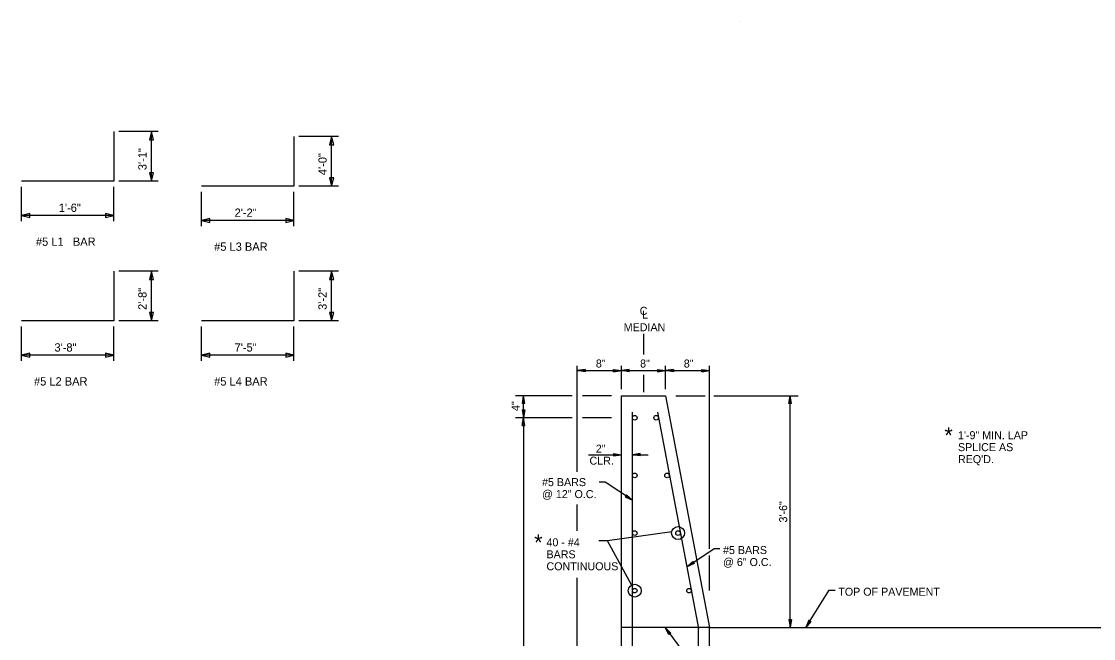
# Model space of a CAD drawing. Extents: x 757924.6 to 757955.2, y 1657125.5 to 1657146.2.
# Drawn here: x 757928.46 to 757944.65, y 1657136.87 to 1657146.19 of the extents above; entities that cross this region are included whole.
import ezdxf

# ---------------------------------------------------------------- set-up
doc = ezdxf.new("R2010")
doc.units = 0
for name, color, linetype in [('1', 7, 'Continuous'), ('2', 7, 'Continuous'), ('7', 7, 'Continuous'), ('9', 7, 'Continuous'), ('R_Border', 7, 'Continuous')]:
    doc.layers.add(name, color=color, linetype=linetype)

msp = doc.modelspace()

# ---------------------------------------------------------------- linework, layer by layer
at = {"layer": '1'}
for p, q in [((757929.851, 1657144.528), (757929.851, 1657143.778)), ((757932.572, 1657144.454), (757932.572, 1657143.704)), ((757929.851, 1657143.778), (757928.455, 1657143.778)), ((757932.572, 1657143.704), (757931.176, 1657143.704)), ((757929.851, 1657142.418), (757929.851, 1657141.669)), ((757932.572, 1657142.418), (757932.572, 1657141.669)), ((757929.851, 1657141.669), (757928.455, 1657141.669)), ((757932.572, 1657141.669), (757931.176, 1657141.669)), ((757937.85, 1657141.472), (757937.85, 1657141.164)), ((757937.85, 1657140.857), (757937.85, 1657140.592)), ((757937.517, 1657135.539), (757937.517, 1657140.539)), ((757937.517, 1657140.539), (757938.184, 1657140.539)), ((757938.184, 1657140.539), (757938.85, 1657137.039)), ((757937.684, 1657135.523), (757937.684, 1657140.289)), ((757938.062, 1657140.289), (757938.684, 1657137.023)), ((757938.85, 1657137.039), (757937.517, 1657137.039)), ((757938.684, 1657132.641), (757938.684, 1657137.023)), ((757938.85, 1657129.997), (757938.85, 1657137.039)), ((757938.85, 1657137.039), (757945.177, 1657137.039))]:
    msp.add_line(p, q, dxfattribs=at)
for centre in [(757937.719, 1657140.206), (757938.043, 1657140.206), (757937.719, 1657139.335), (757938.208, 1657139.335), (757937.719, 1657138.465), (757938.374, 1657138.465), (757937.719, 1657137.595), (757938.54, 1657137.595)]:
    msp.add_circle(centre, 0.0349, dxfattribs=at)
at = {"layer": '7'}
for p, q in [((757936.969, 1657140.937), (757936.85, 1657140.918)), ((757936.969, 1657140.901), (757936.85, 1657140.918)), ((757936.969, 1657140.934), (757936.87, 1657140.918)), ((757936.969, 1657140.904), (757936.87, 1657140.918)), ((757936.969, 1657140.93), (757936.891, 1657140.918)), ((757936.969, 1657140.907), (757936.891, 1657140.918)), ((757936.969, 1657140.928), (757936.911, 1657140.918)), ((757936.969, 1657140.91), (757936.911, 1657140.918)), ((757936.969, 1657140.924), (757936.931, 1657140.918)), ((757936.969, 1657140.913), (757936.931, 1657140.918)), ((757936.969, 1657140.921), (757936.951, 1657140.918)), ((757936.969, 1657140.916), (757936.951, 1657140.918)), ((757936.969, 1657140.937), (757936.969, 1657140.901)), ((757937.397, 1657140.936), (757937.517, 1657140.918)), ((757937.397, 1657140.901), (757937.397, 1657140.936)), ((757937.397, 1657140.933), (757937.497, 1657140.918)), ((757937.397, 1657140.93), (757937.477, 1657140.918)), ((757937.397, 1657140.927), (757937.456, 1657140.918)), ((757937.397, 1657140.924), (757937.436, 1657140.918)), ((757937.397, 1657140.921), (757937.417, 1657140.918)), ((757937.397, 1657140.901), (757937.517, 1657140.918)), ((757937.397, 1657140.913), (757937.436, 1657140.918)), ((757937.397, 1657140.907), (757937.477, 1657140.918)), ((757937.397, 1657140.904), (757937.497, 1657140.918)), ((757937.397, 1657140.91), (757937.456, 1657140.918)), ((757937.397, 1657140.916), (757937.417, 1657140.918)), ((757937.637, 1657140.936), (757937.517, 1657140.918)), ((757937.637, 1657140.901), (757937.517, 1657140.918)), ((757937.637, 1657140.933), (757937.537, 1657140.918)), ((757937.637, 1657140.904), (757937.537, 1657140.918)), ((757937.637, 1657140.93), (757937.558, 1657140.918)), ((757937.637, 1657140.907), (757937.558, 1657140.918)), ((757937.637, 1657140.927), (757937.578, 1657140.918)), ((757937.637, 1657140.91), (757937.578, 1657140.918)), ((757937.637, 1657140.924), (757937.598, 1657140.918)), ((757937.637, 1657140.913), (757937.598, 1657140.918)), ((757937.637, 1657140.921), (757937.618, 1657140.918)), ((757937.637, 1657140.916), (757937.618, 1657140.918)), ((757937.637, 1657140.901), (757937.637, 1657140.936)), ((757938.065, 1657140.937), (757938.184, 1657140.918)), ((757938.065, 1657140.937), (757938.065, 1657140.901)), ((757938.065, 1657140.934), (757938.164, 1657140.918)), ((757938.065, 1657140.93), (757938.143, 1657140.918)), ((757938.065, 1657140.928), (757938.123, 1657140.918)), ((757938.065, 1657140.924), (757938.103, 1657140.918)), ((757938.065, 1657140.921), (757938.083, 1657140.918)), ((757938.065, 1657140.901), (757938.184, 1657140.918)), ((757938.065, 1657140.913), (757938.103, 1657140.918)), ((757938.065, 1657140.907), (757938.143, 1657140.918)), ((757938.065, 1657140.904), (757938.164, 1657140.918)), ((757938.065, 1657140.91), (757938.123, 1657140.918)), ((757938.065, 1657140.916), (757938.083, 1657140.918)), ((757938.303, 1657140.937), (757938.184, 1657140.918)), ((757938.303, 1657140.901), (757938.184, 1657140.918)), ((757938.303, 1657140.934), (757938.203, 1657140.918)), ((757938.303, 1657140.904), (757938.203, 1657140.918)), ((757938.303, 1657140.93), (757938.224, 1657140.918)), ((757938.303, 1657140.907), (757938.224, 1657140.918)), ((757938.303, 1657140.928), (757938.244, 1657140.918)), ((757938.303, 1657140.91), (757938.244, 1657140.918)), ((757938.303, 1657140.924), (757938.264, 1657140.918)), ((757938.303, 1657140.913), (757938.264, 1657140.918)), ((757938.303, 1657140.921), (757938.284, 1657140.918)), ((757938.303, 1657140.916), (757938.284, 1657140.918)), ((757938.303, 1657140.937), (757938.303, 1657140.901)), ((757938.731, 1657140.936), (757938.85, 1657140.918)), ((757938.731, 1657140.901), (757938.731, 1657140.936)), ((757938.731, 1657140.933), (757938.83, 1657140.918)), ((757938.731, 1657140.93), (757938.81, 1657140.918)), ((757938.731, 1657140.927), (757938.79, 1657140.918)), ((757938.731, 1657140.924), (757938.77, 1657140.918)), ((757938.731, 1657140.921), (757938.75, 1657140.918)), ((757938.731, 1657140.901), (757938.85, 1657140.918)), ((757938.731, 1657140.913), (757938.77, 1657140.918)), ((757938.731, 1657140.907), (757938.81, 1657140.918)), ((757938.731, 1657140.904), (757938.83, 1657140.918)), ((757938.731, 1657140.91), (757938.79, 1657140.918)), ((757938.731, 1657140.916), (757938.75, 1657140.918)), ((757936.022, 1657140.42), (757936.04, 1657140.539)), ((757936.025, 1657140.42), (757936.04, 1657140.519)), ((757936.028, 1657140.42), (757936.04, 1657140.499)), ((757936.057, 1657140.42), (757936.04, 1657140.539)), ((757936.054, 1657140.42), (757936.04, 1657140.519)), ((757936.052, 1657140.42), (757936.04, 1657140.499)), ((757940.049, 1657140.42), (757940.067, 1657140.539)), ((757940.052, 1657140.42), (757940.067, 1657140.519)), ((757940.055, 1657140.42), (757940.067, 1657140.499)), ((757940.085, 1657140.42), (757940.067, 1657140.539)), ((757940.082, 1657140.42), (757940.067, 1657140.519)), ((757940.079, 1657140.42), (757940.067, 1657140.499)), ((757936.021, 1657140.325), (757936.04, 1657140.206)), ((757936.021, 1657140.325), (757936.057, 1657140.325)), ((757936.057, 1657140.42), (757936.022, 1657140.42)), ((757936.024, 1657140.325), (757936.04, 1657140.225)), ((757936.028, 1657140.325), (757936.04, 1657140.246)), ((757936.03, 1657140.325), (757936.04, 1657140.267)), ((757936.031, 1657140.42), (757936.04, 1657140.479)), ((757936.034, 1657140.42), (757936.04, 1657140.458)), ((757936.034, 1657140.325), (757936.04, 1657140.286)), ((757936.037, 1657140.42), (757936.04, 1657140.439)), ((757936.037, 1657140.325), (757936.04, 1657140.306)), ((757936.049, 1657140.42), (757936.04, 1657140.479)), ((757936.046, 1657140.42), (757936.04, 1657140.458)), ((757936.042, 1657140.42), (757936.04, 1657140.439)), ((757936.057, 1657140.325), (757936.04, 1657140.206)), ((757936.045, 1657140.325), (757936.04, 1657140.286)), ((757936.051, 1657140.325), (757936.04, 1657140.246)), ((757936.054, 1657140.325), (757936.04, 1657140.225)), ((757936.048, 1657140.325), (757936.04, 1657140.267)), ((757936.042, 1657140.325), (757936.04, 1657140.306)), ((757940.085, 1657140.42), (757940.049, 1657140.42)), ((757940.058, 1657140.42), (757940.067, 1657140.478)), ((757940.061, 1657140.42), (757940.067, 1657140.458)), ((757940.064, 1657140.42), (757940.067, 1657140.439)), ((757940.076, 1657140.42), (757940.067, 1657140.478)), ((757940.073, 1657140.42), (757940.067, 1657140.458)), ((757940.07, 1657140.42), (757940.067, 1657140.439)), ((757936.021, 1657140.087), (757936.04, 1657140.206)), ((757936.024, 1657140.087), (757936.04, 1657140.186)), ((757936.028, 1657140.087), (757936.04, 1657140.165)), ((757936.057, 1657140.087), (757936.04, 1657140.206)), ((757936.054, 1657140.087), (757936.04, 1657140.186)), ((757936.051, 1657140.087), (757936.04, 1657140.165)), ((757936.021, 1657140.087), (757936.057, 1657140.087)), ((757936.03, 1657140.087), (757936.04, 1657140.145)), ((757936.034, 1657140.087), (757936.04, 1657140.126)), ((757936.037, 1657140.087), (757936.04, 1657140.105)), ((757936.048, 1657140.087), (757936.04, 1657140.145)), ((757936.045, 1657140.087), (757936.04, 1657140.126)), ((757936.042, 1657140.087), (757936.04, 1657140.105)), ((757937.398, 1657139.666), (757937.517, 1657139.647)), ((757937.398, 1657139.666), (757937.398, 1657139.63)), ((757937.398, 1657139.663), (757937.497, 1657139.647)), ((757937.398, 1657139.659), (757937.477, 1657139.647)), ((757937.398, 1657139.657), (757937.456, 1657139.647)), ((757937.398, 1657139.653), (757937.437, 1657139.647)), ((757937.398, 1657139.65), (757937.417, 1657139.647)), ((757937.398, 1657139.63), (757937.517, 1657139.647)), ((757937.398, 1657139.642), (757937.437, 1657139.647)), ((757937.398, 1657139.636), (757937.477, 1657139.647)), ((757937.398, 1657139.633), (757937.497, 1657139.647)), ((757937.398, 1657139.639), (757937.456, 1657139.647)), ((757937.398, 1657139.645), (757937.417, 1657139.647)), ((757937.803, 1657139.665), (757937.684, 1657139.647)), ((757937.803, 1657139.629), (757937.684, 1657139.647)), ((757937.803, 1657139.662), (757937.704, 1657139.647)), ((757937.803, 1657139.633), (757937.704, 1657139.647)), ((757937.803, 1657139.659), (757937.725, 1657139.647)), ((757937.803, 1657139.635), (757937.725, 1657139.647)), ((757937.803, 1657139.656), (757937.744, 1657139.647)), ((757937.803, 1657139.638), (757937.744, 1657139.647)), ((757937.803, 1657139.653), (757937.764, 1657139.647)), ((757937.803, 1657139.641), (757937.764, 1657139.647)), ((757937.803, 1657139.65), (757937.784, 1657139.647)), ((757937.803, 1657139.644), (757937.784, 1657139.647)), ((757937.803, 1657139.629), (757937.803, 1657139.665)), ((757937.595, 1657139.042), (757937.575, 1657139.012)), ((757937.583, 1657139.025), (757937.6, 1657139.016)), ((757937.586, 1657139.029), (757937.6, 1657139.016)), ((757937.588, 1657139.032), (757937.617, 1657139.005)), ((757937.589, 1657139.034), (757937.633, 1657138.994)), ((757937.591, 1657139.036), (757937.65, 1657138.983)), ((757937.593, 1657139.039), (757937.667, 1657138.971)), ((757937.595, 1657139.042), (757937.684, 1657138.96)), ((757937.575, 1657139.012), (757937.684, 1657138.96)), ((757937.576, 1657139.014), (757937.667, 1657138.971)), ((757937.578, 1657139.017), (757937.65, 1657138.983)), ((757937.579, 1657139.019), (757937.633, 1657138.994)), ((757937.581, 1657139.022), (757937.617, 1657139.005)), ((757938.595, 1657138.038), (757938.506, 1657137.956)), ((757938.615, 1657138.007), (757938.506, 1657137.956)), ((757938.597, 1657138.035), (757938.523, 1657137.967)), ((757938.614, 1657138.01), (757938.523, 1657137.967)), ((757938.599, 1657138.032), (757938.54, 1657137.978)), ((757938.612, 1657138.013), (757938.54, 1657137.978)), ((757938.6, 1657138.03), (757938.557, 1657137.99)), ((757938.61, 1657138.015), (757938.557, 1657137.99)), ((757938.602, 1657138.027), (757938.573, 1657138)), ((757938.608, 1657138.018), (757938.573, 1657138)), ((757938.604, 1657138.025), (757938.59, 1657138.012)), ((757938.607, 1657138.02), (757938.59, 1657138.012)), ((757938.595, 1657138.038), (757938.615, 1657138.007)), ((757940.049, 1657137.158), (757940.067, 1657137.039)), ((757940.049, 1657137.158), (757940.085, 1657137.158)), ((757940.052, 1657137.158), (757940.067, 1657137.059)), ((757940.055, 1657137.158), (757940.067, 1657137.08)), ((757940.058, 1657137.158), (757940.067, 1657137.1)), ((757940.061, 1657137.158), (757940.067, 1657137.119)), ((757940.064, 1657137.158), (757940.067, 1657137.14)), ((757940.085, 1657137.158), (757940.067, 1657137.039)), ((757940.073, 1657137.158), (757940.067, 1657137.119)), ((757940.078, 1657137.158), (757940.067, 1657137.08)), ((757940.081, 1657137.158), (757940.067, 1657137.059)), ((757940.076, 1657137.158), (757940.067, 1657137.1)), ((757940.07, 1657137.158), (757940.067, 1657137.14)), ((757940.35, 1657137.15), (757940.302, 1657137.039)), ((757940.381, 1657137.13), (757940.302, 1657137.039)), ((757940.353, 1657137.148), (757940.313, 1657137.056)), ((757940.378, 1657137.132), (757940.313, 1657137.056)), ((757940.356, 1657137.146), (757940.323, 1657137.073)), ((757940.375, 1657137.134), (757940.323, 1657137.073)), ((757940.358, 1657137.145), (757940.334, 1657137.09)), ((757940.373, 1657137.135), (757940.334, 1657137.09)), ((757940.361, 1657137.143), (757940.345, 1657137.107)), ((757940.37, 1657137.137), (757940.345, 1657137.107)), ((757940.35, 1657137.15), (757940.381, 1657137.13)), ((757940.363, 1657137.142), (757940.356, 1657137.124)), ((757940.368, 1657137.139), (757940.356, 1657137.124)), ((757938.264, 1657136.954), (757938.178, 1657137.039)), ((757938.235, 1657136.933), (757938.178, 1657137.039)), ((757938.261, 1657136.952), (757938.19, 1657137.023)), ((757938.237, 1657136.934), (757938.19, 1657137.023)), ((757938.24, 1657136.937), (757938.202, 1657137.007)), ((757938.258, 1657136.95), (757938.202, 1657137.007)), ((757938.256, 1657136.949), (757938.214, 1657136.991)), ((757938.242, 1657136.938), (757938.214, 1657136.991)), ((757938.245, 1657136.94), (757938.226, 1657136.975)), ((757938.254, 1657136.947), (757938.226, 1657136.975)), ((757938.264, 1657136.954), (757938.235, 1657136.933)), ((757938.247, 1657136.942), (757938.238, 1657136.959)), ((757938.251, 1657136.945), (757938.238, 1657136.959))]:
    msp.add_line(p, q, dxfattribs=at)
at = {"layer": '9'}
for p, q in [((757930.521, 1657144.528), (757929.924, 1657144.528)), ((757930.42, 1657143.778), (757930.42, 1657144.528)), ((757933.242, 1657144.454), (757932.645, 1657144.454)), ((757933.141, 1657143.704), (757933.141, 1657144.454)), ((757930.521, 1657143.778), (757929.924, 1657143.778)), ((757928.455, 1657143.175), (757928.455, 1657143.694)), ((757929.851, 1657143.175), (757929.851, 1657143.694)), ((757931.176, 1657143.1), (757931.176, 1657143.62)), ((757932.572, 1657143.1), (757932.572, 1657143.62)), ((757933.242, 1657143.704), (757932.645, 1657143.704)), ((757929.851, 1657143.26), (757928.455, 1657143.26)), ((757932.572, 1657143.186), (757931.176, 1657143.186)), ((757930.521, 1657142.418), (757929.924, 1657142.418)), ((757930.42, 1657141.669), (757930.42, 1657142.418)), ((757933.242, 1657142.418), (757932.645, 1657142.418)), ((757933.141, 1657141.669), (757933.141, 1657142.418)), ((757930.521, 1657141.669), (757929.924, 1657141.669)), ((757933.242, 1657141.669), (757932.645, 1657141.669)), ((757928.455, 1657141.065), (757928.455, 1657141.584)), ((757929.851, 1657141.065), (757929.851, 1657141.584)), ((757931.176, 1657141.065), (757931.176, 1657141.584)), ((757932.572, 1657141.065), (757932.572, 1657141.584)), ((757929.851, 1657141.15), (757928.455, 1657141.15)), ((757932.572, 1657141.15), (757931.176, 1657141.15)), ((757936.85, 1657139.392), (757936.85, 1657140.991)), ((757937.517, 1657140.638), (757937.517, 1657140.991)), ((757938.184, 1657140.638), (757938.184, 1657140.991)), ((757938.85, 1657138.226), (757938.85, 1657140.991)), ((757936.85, 1657140.918), (757938.85, 1657140.918)), ((757936.772, 1657140.539), (757935.92, 1657140.539)), ((757936.04, 1657140.206), (757936.04, 1657140.539)), ((757937.367, 1657140.539), (757936.931, 1657140.539)), ((757938.34, 1657140.539), (757938.784, 1657140.539)), ((757938.914, 1657140.539), (757940.187, 1657140.539)), ((757940.067, 1657138.059), (757940.067, 1657140.539)), ((757936.772, 1657140.206), (757935.92, 1657140.206)), ((757936.04, 1657140.206), (757936.04, 1657138.897)), ((757937.367, 1657140.206), (757936.931, 1657140.206)), ((757937.022, 1657139.647), (757937.517, 1657139.647)), ((757937.684, 1657139.647), (757937.921, 1657139.647)), ((757937.273, 1657139.236), (757937.183, 1657139.236)), ((757937.684, 1657138.96), (757937.273, 1657139.236)), ((757936.04, 1657138.897), (757936.04, 1657132.373)), ((757936.85, 1657138.5), (757936.85, 1657138.897)), ((757938.278, 1657138.483), (757937.308, 1657138.349)), ((757937.308, 1657138.349), (757937.175, 1657138.349)), ((757937.672, 1657137.681), (757937.308, 1657138.349)), ((757938.506, 1657137.956), (757938.917, 1657138.232)), ((757938.917, 1657138.232), (757939.007, 1657138.232)), ((757938.85, 1657137.599), (757938.85, 1657138.125)), ((757940.067, 1657137.039), (757940.067, 1657138.059)), ((757936.85, 1657132.51), (757936.85, 1657137.787)), ((757940.302, 1657137.039), (757940.658, 1657137.603)), ((757940.658, 1657137.603), (757940.748, 1657137.603)), ((757938.178, 1657137.039), (757939.055, 1657135.86))]:
    msp.add_line(p, q, dxfattribs=at)
for points in [[(757930.451, 1657144.403), (757930.42, 1657144.528), (757930.388, 1657144.403)], [(757933.172, 1657144.329), (757933.141, 1657144.454), (757933.11, 1657144.329)], [(757930.388, 1657143.903), (757930.42, 1657143.778), (757930.451, 1657143.903)], [(757933.11, 1657143.829), (757933.141, 1657143.704), (757933.172, 1657143.829)], [(757928.58, 1657143.291), (757928.455, 1657143.26), (757928.58, 1657143.229)], [(757929.726, 1657143.229), (757929.851, 1657143.26), (757929.726, 1657143.291)], [(757931.301, 1657143.217), (757931.176, 1657143.186), (757931.301, 1657143.154)], [(757932.447, 1657143.154), (757932.572, 1657143.186), (757932.447, 1657143.217)], [(757930.451, 1657142.293), (757930.42, 1657142.418), (757930.388, 1657142.293)], [(757933.172, 1657142.293), (757933.141, 1657142.418), (757933.11, 1657142.293)], [(757930.388, 1657141.794), (757930.42, 1657141.669), (757930.451, 1657141.794)], [(757933.11, 1657141.794), (757933.141, 1657141.669), (757933.172, 1657141.794)], [(757928.58, 1657141.181), (757928.455, 1657141.15), (757928.58, 1657141.119)], [(757929.726, 1657141.119), (757929.851, 1657141.15), (757929.726, 1657141.181)], [(757931.301, 1657141.181), (757931.176, 1657141.15), (757931.301, 1657141.119)], [(757932.447, 1657141.119), (757932.572, 1657141.15), (757932.447, 1657141.181)]]:
    msp.add_lwpolyline(points, close=True, dxfattribs=at)
for centre in [(757938.374, 1657138.465), (757937.719, 1657137.595)]:
    msp.add_circle(centre, 0.0979, dxfattribs=at)
at = {"layer": 'R_Border'}
msp.add_line((757939.309, 1657146.191), (757939.309, 1657146.191), dxfattribs=at)
msp.add_line((757939.309, 1657146.191), (757939.309, 1657146.191), dxfattribs=at)

# ---------------------------------------------------------------- texts
at = {"layer": '2'}
for s, height, p in [('3\'-1"', 0.125, (757930.345, 1657143.945)), ('4\'-0"', 0.125, (757933.066, 1657143.87)), ('2\'-8"', 0.125, (757930.345, 1657141.835)), ('3\'-2"', 0.125, (757933.066, 1657141.835)), ('4"', 0.1209, (757935.979, 1657140.308)), ('3\'-6"', 0.1209, (757940.022, 1657138.624))]:
    msp.add_text(s, height=height, rotation=90, dxfattribs=at).set_placement(p)
for s, height, p in [('1\'-6"', 0.125, (757929.019, 1657143.315)), ('2\'-2"', 0.125, (757931.675, 1657143.241)), ('#5 L1   BAR', 0.125, (757928.674, 1657142.803)), ('#5 L3 BAR', 0.125, (757931.366, 1657142.728)), ('C', 0.121, (757937.795, 1657141.76)), ('L', 0.121, (757937.831, 1657141.704)), ('MEDIAN', 0.1208, (757937.553, 1657141.513)), ('3\'-8"', 0.125, (757928.954, 1657141.206)), ('7\'-5"', 0.125, (757931.675, 1657141.206)), ('8"', 0.1209, (757937.132, 1657140.965)), ('8"', 0.1209, (757937.8, 1657140.965)), ('8"', 0.1209, (757938.46, 1657140.965)), ('#5 L2 BAR', 0.125, (757928.645, 1657140.693)), ('#5 L4 BAR', 0.125, (757931.366, 1657140.693)), ('*', 0.242, (757942.397, 1657139.821)), ('1\'-9" MIN. LAP', 0.12081, (757942.602, 1657139.883)), ('2"', 0.1209, (757937.131, 1657139.679)), ('SPLICE AS', 0.1208, (757942.602, 1657139.702)), ('CLR.', 0.1209, (757937.036, 1657139.498)), ("REQ'D.", 0.1208, (757942.602, 1657139.521)), ('#5 BARS', 0.1208, (757936.319, 1657139.174)), ('@ 12" O.C.', 0.1208, (757936.319, 1657138.993)), ('*', 0.242, (757936.2, 1657138.203)), ('40 - #4', 0.1208, (757936.386, 1657138.265)), ('#5 BARS', 0.1208, (757939.053, 1657138.148)), ('BARS', 0.1208, (757936.386, 1657138.084)), ('@ 6" O.C.', 0.1208, (757939.053, 1657137.967)), ('CONTINUOUS', 0.1208, (757936.386, 1657137.903)), ('TOP OF PAVEMENT', 0.12081, (757940.794, 1657137.519))]:
    msp.add_text(s, height=height, dxfattribs=at).set_placement(p)

doc.saveas('drawing.dxf')
